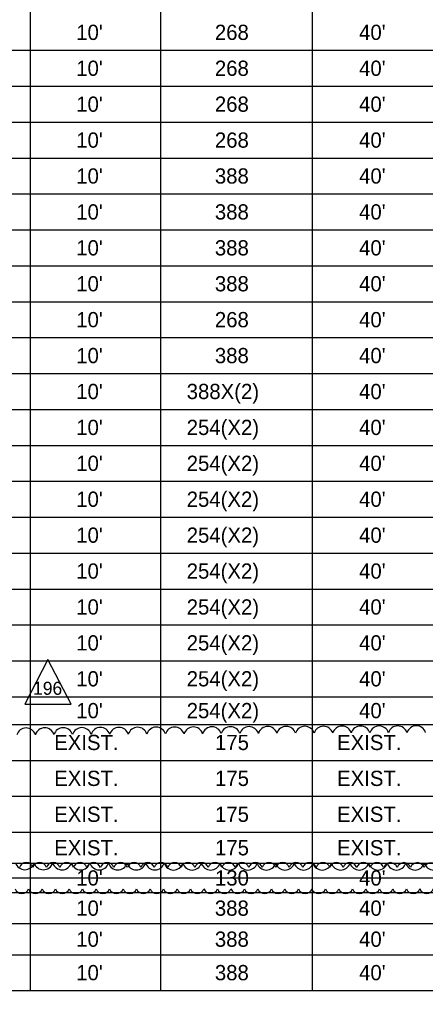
# Model space of a CAD drawing. Extents: x -818.1 to -802.4, y -2221.2 to -2187.7.
# Drawn here: x -814.295 to -812.426, y -2206.269 to -2201.807 of the extents above; entities that cross this region are included whole.
import ezdxf

# ---------------------------------------------------------------- set-up
doc = ezdxf.new("R2010")
doc.units = 0
for name, color, linetype in [('PlotBorder_dp', 7, 'Continuous'), ('SheetBorder_dp', 7, 'Continuous'), ('SheetLines_dp', 7, 'Continuous'), ('TextMinor', 7, 'Continuous'), ('TextTitle', 7, 'Continuous')]:
    doc.layers.add(name, color=color, linetype=linetype)

msp = doc.modelspace()

# ---------------------------------------------------------------- linework, layer by layer
at = {"layer": 'PlotBorder_dp'}
for p, q in [((-814.2457, -2199.8042), (-814.2457, -2206.2692)), ((-814.2457, -2199.8042), (-814.2457, -2206.2692)), ((-813.6457, -2199.8042), (-813.6457, -2206.2692)), ((-813.6457, -2199.8042), (-813.6457, -2206.2692)), ((-812.9482, -2199.8042), (-812.9482, -2206.2692)), ((-812.9482, -2199.8042), (-812.9482, -2206.2692))]:
    msp.add_line(p, q, dxfattribs=at)
at = {"layer": 'SheetLines_dp'}
msp.add_line((-817.2082, -2206.2692), (-811.1482, -2206.2692), dxfattribs=at)
at = {"layer": 'TextMinor'}
for p, q in [((-817.2082, -2201.9492), (-809.6857, -2201.9492)), ((-817.2082, -2201.9492), (-809.6857, -2201.9492)), ((-817.2082, -2202.1142), (-809.6857, -2202.1142)), ((-817.2082, -2202.1142), (-809.6857, -2202.1142)), ((-817.2082, -2202.2792), (-809.6857, -2202.2792)), ((-817.2082, -2202.2792), (-809.6857, -2202.2792)), ((-817.2082, -2202.4442), (-809.6857, -2202.4442)), ((-817.2082, -2202.4442), (-809.6857, -2202.4442)), ((-817.2082, -2202.6092), (-809.6857, -2202.6092)), ((-817.2082, -2202.6092), (-809.6857, -2202.6092)), ((-817.2082, -2202.7742), (-809.6857, -2202.7742)), ((-817.2082, -2202.7742), (-809.6857, -2202.7742)), ((-817.2082, -2202.9392), (-809.6857, -2202.9392)), ((-817.2082, -2202.9392), (-809.6857, -2202.9392)), ((-817.2082, -2203.1042), (-809.6857, -2203.1042)), ((-817.2082, -2203.1042), (-809.6857, -2203.1042)), ((-817.2082, -2203.2692), (-809.6857, -2203.2692)), ((-817.2082, -2203.2692), (-809.6857, -2203.2692)), ((-817.2082, -2203.4342), (-809.6857, -2203.4342)), ((-817.2082, -2203.4342), (-809.6857, -2203.4342)), ((-817.2082, -2203.5992), (-809.6857, -2203.5992)), ((-817.2082, -2203.5992), (-809.6857, -2203.5992)), ((-817.2082, -2203.7642), (-809.6857, -2203.7642)), ((-817.2082, -2203.7642), (-809.6857, -2203.7642)), ((-817.2082, -2203.9292), (-809.6857, -2203.9292)), ((-817.2082, -2203.9292), (-809.6857, -2203.9292)), ((-817.2082, -2204.0942), (-809.6857, -2204.0942)), ((-817.2082, -2204.0942), (-809.6857, -2204.0942)), ((-817.2082, -2204.2592), (-809.6857, -2204.2592)), ((-817.2082, -2204.2592), (-809.6857, -2204.2592)), ((-817.2082, -2204.4242), (-809.6857, -2204.4242)), ((-817.2082, -2204.4242), (-809.6857, -2204.4242)), ((-817.2082, -2204.5892), (-809.6857, -2204.5892)), ((-817.2082, -2204.5892), (-809.6857, -2204.5892)), ((-817.2082, -2204.7542), (-809.6857, -2204.7542)), ((-817.2082, -2204.7542), (-809.6857, -2204.7542)), ((-817.2082, -2204.9192), (-809.6857, -2204.9192)), ((-816.2257, -2204.9192), (-809.6857, -2204.9192)), ((-817.2082, -2205.0467), (-809.6857, -2205.0467)), ((-817.2082, -2205.0467), (-809.6857, -2205.0467)), ((-817.2082, -2205.2117), (-809.6857, -2205.2117)), ((-814.2457, -2205.2117), (-809.6857, -2205.2117)), ((-817.2082, -2205.3767), (-813.6457, -2205.3767)), ((-817.2082, -2205.3767), (-809.6857, -2205.3767)), ((-812.9482, -2205.3767), (-809.6857, -2205.3767)), ((-817.2082, -2205.5417), (-809.6857, -2205.5417)), ((-814.2457, -2205.5417), (-809.6857, -2205.5417)), ((-817.2082, -2205.6842), (-809.6857, -2205.6842)), ((-814.2457, -2205.6842), (-813.6457, -2205.6842)), ((-812.9482, -2205.6842), (-809.6857, -2205.6842)), ((-817.2082, -2205.8192), (-809.6857, -2205.8192)), ((-816.7882, -2205.8192), (-811.1482, -2205.8192)), ((-817.2082, -2205.9617), (-809.6857, -2205.9617)), ((-816.2257, -2205.9617), (-814.2457, -2205.9617)), ((-817.2082, -2206.1042), (-809.6857, -2206.1042)), ((-813.6457, -2206.1042), (-811.1482, -2206.1042))]:
    msp.add_line(p, q, dxfattribs=at)
at = {"layer": 'TextTitle'}
msp.add_line((-817.0974, -2205.7517), (-809.7376, -2205.7517), dxfattribs=at)
msp.add_lwpolyline([(-814.1639, -2204.7479), (-814.2705, -2204.9531), (-814.0574, -2204.9531)], close=True, dxfattribs=at)
for centre, radius, start, end in [((-814.264, -2205.1074), 0.0448, 17.8707, 162.8707), ((-814.1786, -2205.1068), 0.0448, 17.8645, 162.8645), ((-814.0931, -2205.1063), 0.0448, 17.8587, 162.8587), ((-814.0076, -2205.1058), 0.0448, 17.8533, 162.8533), ((-813.9222, -2205.1052), 0.0448, 17.8482, 162.8482), ((-813.8367, -2205.1047), 0.0448, 17.8434, 162.8434), ((-813.7512, -2205.1042), 0.0448, 17.8389, 162.8389), ((-813.6657, -2205.1037), 0.0448, 17.8346, 162.8346), ((-813.5803, -2205.1032), 0.0448, 17.8305, 162.8305), ((-813.4948, -2205.1027), 0.0448, 17.8266, 162.8266), ((-813.4093, -2205.1022), 0.0448, 17.823, 162.823), ((-813.3238, -2205.1018), 0.0448, 17.8195, 162.8195), ((-813.2384, -2205.1013), 0.0448, 17.8161, 162.8161), ((-813.1529, -2205.1008), 0.0448, 17.8129, 162.8129), ((-813.0674, -2205.1003), 0.0448, 17.8098, 162.8098), ((-812.982, -2205.0999), 0.0448, 17.8016, 162.8016), ((-812.8965, -2205.0995), 0.0448, 17.7899, 162.7899), ((-812.811, -2205.099), 0.0448, 17.7775, 162.7775), ((-812.7255, -2205.0986), 0.0448, 17.7646, 162.7646), ((-812.6401, -2205.0982), 0.0448, 17.7511, 162.7511), ((-812.5546, -2205.0979), 0.0448, 17.737, 162.737), ((-812.4691, -2205.0975), 0.0448, 17.7221, 162.7221), ((-814.2698, -2205.6691), 0.0448, 197.3358, 342.3358), ((-814.2639, -2205.7136), 0.0325, 17.4964, 162.4964), ((-814.2018, -2205.7136), 0.0325, 17.4968, 162.4968), ((-814.1843, -2205.6694), 0.0448, 197.3521, 342.3521), ((-814.1398, -2205.7136), 0.0325, 17.4971, 162.4971), ((-814.0989, -2205.6696), 0.0448, 197.3673, 342.3673), ((-814.0777, -2205.7136), 0.0325, 17.4974, 162.4974), ((-814.0134, -2205.6698), 0.0448, 197.3816, 342.3816), ((-814.0157, -2205.7136), 0.0325, 17.4978, 162.4978), ((-813.9536, -2205.7137), 0.0325, 17.4981, 162.4981), ((-813.9279, -2205.6699), 0.0448, 197.395, 342.395), ((-813.8915, -2205.7137), 0.0325, 17.4984, 162.4984), ((-813.8424, -2205.6701), 0.0448, 197.4077, 342.4077), ((-813.8295, -2205.7137), 0.0325, 17.4986, 162.4986), ((-813.757, -2205.6702), 0.0448, 197.4196, 342.4196), ((-813.7674, -2205.7137), 0.0325, 17.4989, 162.4989), ((-813.7054, -2205.7137), 0.0325, 17.4992, 162.4992), ((-813.6715, -2205.6703), 0.0448, 197.4309, 342.4309), ((-813.6433, -2205.7137), 0.0325, 17.4995, 162.4995), ((-813.586, -2205.6704), 0.0448, 197.4416, 342.4416), ((-813.5812, -2205.7137), 0.0325, 17.4997, 162.4997), ((-813.5192, -2205.7137), 0.0325, 17.4998, 162.4998), ((-813.5005, -2205.6705), 0.0448, 197.4518, 342.4518), ((-813.4571, -2205.7137), 0.0325, 17.4986, 162.4986), ((-813.4151, -2205.6706), 0.0448, 197.4615, 342.4615), ((-813.3951, -2205.7137), 0.0325, 17.497, 162.497), ((-813.3296, -2205.6706), 0.0448, 197.4707, 342.4707), ((-813.333, -2205.7137), 0.0325, 17.4953, 162.4953), ((-813.271, -2205.7137), 0.0325, 17.4935, 162.4935), ((-813.2441, -2205.6706), 0.0448, 197.4795, 342.4795), ((-813.2089, -2205.7137), 0.0325, 17.4918, 162.4918), ((-813.1586, -2205.6707), 0.0448, 197.4879, 342.4879), ((-813.1468, -2205.7137), 0.0325, 17.4899, 162.4899), ((-813.0732, -2205.6707), 0.0448, 197.496, 342.496), ((-813.0848, -2205.7137), 0.0325, 17.4881, 162.4881), ((-813.0227, -2205.7137), 0.0325, 17.4861, 162.4861), ((-812.9877, -2205.6707), 0.0448, 197.5026, 342.5026), ((-812.9607, -2205.7137), 0.0325, 17.4841, 162.4841), ((-812.9022, -2205.6707), 0.0448, 197.5082, 342.5082), ((-812.8986, -2205.7138), 0.0325, 17.4821, 162.4821), ((-812.8366, -2205.7138), 0.0325, 17.48, 162.48), ((-812.8168, -2205.6707), 0.0448, 197.514, 342.514), ((-812.7745, -2205.7138), 0.0325, 17.4778, 162.4778), ((-812.7313, -2205.6706), 0.0448, 197.5201, 342.5201), ((-812.7124, -2205.7138), 0.0325, 17.4755, 162.4755), ((-812.6458, -2205.6706), 0.0448, 197.5265, 342.5265), ((-812.6504, -2205.7138), 0.0325, 17.4732, 162.4732), ((-812.5883, -2205.7139), 0.0325, 17.4708, 162.4708), ((-812.5603, -2205.6705), 0.0448, 197.5333, 342.5333), ((-812.5263, -2205.7139), 0.0325, 17.4683, 162.4683), ((-812.4749, -2205.6705), 0.0448, 197.5403, 342.5403), ((-812.4642, -2205.7139), 0.0325, 17.4657, 162.4657), ((-812.4021, -2205.714), 0.0325, 17.463, 162.463), ((-812.3894, -2205.6704), 0.0448, 197.5477, 342.5477), ((-814.2836, -2205.7912), 0.0325, 197.4765, 342.4765), ((-814.2215, -2205.7913), 0.0325, 197.4786, 342.4786), ((-814.1594, -2205.7913), 0.0325, 197.4807, 342.4807), ((-814.0974, -2205.7913), 0.0325, 197.4827, 342.4827), ((-814.0353, -2205.7913), 0.0325, 197.4846, 342.4846), ((-813.9733, -2205.7913), 0.0325, 197.4865, 342.4865), ((-813.9112, -2205.7913), 0.0325, 197.4883, 342.4883), ((-813.8492, -2205.7914), 0.0325, 197.4901, 342.4901), ((-813.7871, -2205.7914), 0.0325, 197.4918, 342.4918), ((-813.725, -2205.7914), 0.0325, 197.4935, 342.4935), ((-813.663, -2205.7914), 0.0325, 197.4951, 342.4951), ((-813.6009, -2205.7914), 0.0325, 197.4967, 342.4967), ((-813.5389, -2205.7914), 0.0325, 197.4983, 342.4983), ((-813.4768, -2205.7914), 0.0325, 197.4998, 342.4998), ((-813.4148, -2205.7914), 0.0325, 197.5012, 342.5012), ((-813.3527, -2205.7914), 0.0325, 197.5025, 342.5025), ((-813.2906, -2205.7914), 0.0325, 197.5039, 342.5039), ((-813.2286, -2205.7914), 0.0325, 197.5054, 342.5054), ((-813.1665, -2205.7914), 0.0325, 197.5069, 342.5069), ((-813.1045, -2205.7914), 0.0325, 197.5084, 342.5084), ((-813.0424, -2205.7914), 0.0325, 197.51, 342.51), ((-812.9803, -2205.7913), 0.0325, 197.5116, 342.5116), ((-812.9183, -2205.7913), 0.0325, 197.5133, 342.5133), ((-812.8562, -2205.7913), 0.0325, 197.515, 342.515), ((-812.7942, -2205.7913), 0.0325, 197.5168, 342.5168), ((-812.7321, -2205.7913), 0.0325, 197.5186, 342.5186), ((-812.6701, -2205.7913), 0.0325, 197.5205, 342.5205), ((-812.608, -2205.7912), 0.0325, 197.5224, 342.5224), ((-812.5459, -2205.7912), 0.0325, 197.5245, 342.5245), ((-812.4839, -2205.7912), 0.0325, 197.5265, 342.5265), ((-812.4218, -2205.7911), 0.0325, 197.5287, 342.5287)]:
    msp.add_arc(centre, radius, start, end, dxfattribs=at)

# ---------------------------------------------------------------- texts
at = {"layer": 'SheetBorder_dp'}
for s, p in [("10'", (-814.0336, -2201.9017)), ('268', (-813.3958, -2201.9017)), ("40'", (-812.7324, -2201.9017)), ("10'", (-814.0336, -2202.0667)), ('268', (-813.3958, -2202.0667)), ("40'", (-812.7324, -2202.0667)), ("10'", (-814.0336, -2202.2317)), ('268', (-813.3958, -2202.2317)), ("40'", (-812.7324, -2202.2317)), ("10'", (-814.0336, -2202.3967)), ('268', (-813.3958, -2202.3967)), ("40'", (-812.7324, -2202.3967)), ("10'", (-814.0336, -2202.5617)), ('388', (-813.3958, -2202.5617)), ("40'", (-812.7324, -2202.5617)), ("10'", (-814.0336, -2202.7267)), ('388', (-813.3958, -2202.7267)), ("40'", (-812.7324, -2202.7267)), ("10'", (-814.0336, -2202.8917)), ('388', (-813.3958, -2202.8917)), ("40'", (-812.7324, -2202.8917)), ("10'", (-814.0336, -2203.0567)), ('388', (-813.3958, -2203.0567)), ("40'", (-812.7324, -2203.0567)), ("10'", (-814.0336, -2203.2217)), ('268', (-813.3958, -2203.2217)), ("40'", (-812.7324, -2203.2217)), ("10'", (-814.0336, -2203.3867)), ('388', (-813.3958, -2203.3867)), ("40'", (-812.7324, -2203.3867)), ("10'", (-814.0336, -2203.5517)), ('388X(2)', (-813.5254, -2203.5517)), ("40'", (-812.7324, -2203.5517)), ("10'", (-814.0336, -2203.7167)), ('254(X2)', (-813.5254, -2203.7167)), ("40'", (-812.7324, -2203.7167)), ("10'", (-814.0336, -2203.8817)), ('254(X2)', (-813.5254, -2203.8817)), ("40'", (-812.7324, -2203.8817)), ("10'", (-814.0336, -2204.0467)), ('254(X2)', (-813.5254, -2204.0467)), ("40'", (-812.7324, -2204.0467)), ("10'", (-814.0336, -2204.2117)), ('254(X2)', (-813.5254, -2204.2117)), ("40'", (-812.7324, -2204.2117)), ("10'", (-814.0336, -2204.3767)), ('254(X2)', (-813.5254, -2204.3767)), ("40'", (-812.7324, -2204.3767)), ("10'", (-814.0336, -2204.5417)), ('254(X2)', (-813.5254, -2204.5417)), ("40'", (-812.7324, -2204.5417)), ("10'", (-814.0336, -2204.7067)), ('254(X2)', (-813.5254, -2204.7067)), ("40'", (-812.7324, -2204.7067)), ("10'", (-814.0336, -2204.8717)), ('254(X2)', (-813.5254, -2204.8717)), ("40'", (-812.7324, -2204.8717)), ("10'", (-814.0336, -2205.0179)), ('254(X2)', (-813.5254, -2205.0179)), ("40'", (-812.7324, -2205.0179)), ('EXIST.', (-814.135, -2205.1642)), ('175', (-813.3952, -2205.1642)), ('EXIST.', (-812.8337, -2205.1642)), ('EXIST.', (-814.135, -2205.3292)), ('175', (-813.3952, -2205.3292)), ('EXIST.', (-812.8337, -2205.3292)), ('EXIST.', (-814.135, -2205.4942)), ('175', (-813.3952, -2205.4942)), ('EXIST.', (-812.8337, -2205.4942)), ('EXIST.', (-814.135, -2205.6479)), ('175', (-813.3952, -2205.6479)), ('EXIST.', (-812.8337, -2205.6479)), ("10'", (-814.0336, -2205.7867)), ('130', (-813.3955, -2205.7867)), ("40'", (-812.7324, -2205.7867)), ("10'", (-814.0336, -2205.9254)), ('388', (-813.3958, -2205.9254)), ("40'", (-812.7324, -2205.9254)), ("10'", (-814.0336, -2206.0679)), ('388', (-813.3958, -2206.0679)), ("40'", (-812.7324, -2206.0679)), ("10'", (-814.0336, -2206.2217)), ('388', (-813.3958, -2206.2217)), ("40'", (-812.7324, -2206.2217))]:
    msp.add_text(s, height=0.07, dxfattribs=at).set_placement(p)
at = {"layer": 'TextTitle'}
msp.add_text('196', height=0.06, dxfattribs=at).set_placement((-814.2319, -2204.9103))

doc.saveas('drawing.dxf')
